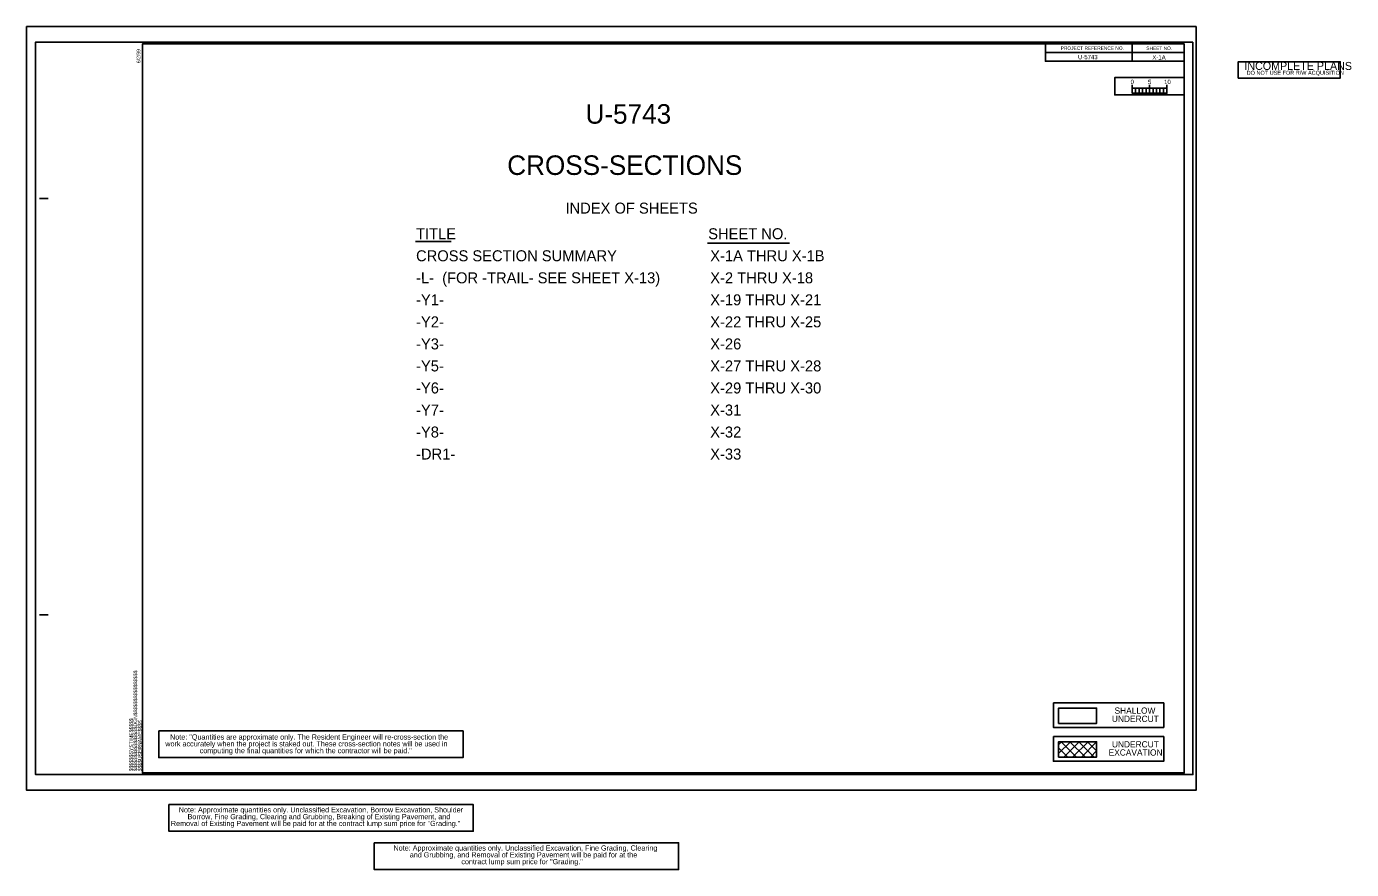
# Model space of a CAD drawing. Extents: x -19 to 363, y -23 to 220.
import ezdxf

# ---------------------------------------------------------------- set-up
doc = ezdxf.new("R2010")
doc.units = 0
for name, color, linetype in [('Old_Level_2', 7, 'Continuous'), ('Old_Level_38', 7, 'Continuous'), ('Old_Level_40', 7, 'Continuous'), ('Old_Level_41', 7, 'Continuous'), ('Prop Grid Mask', 7, 'Continuous'), ('Prop Shade Light', 7, 'Continuous'), ('Prop XS Sheet Number', 7, 'Continuous'), ('Prop XS Undercut Exc Hatch', 7, 'Continuous'), ('Prop XSC Text', 7, 'Continuous'), ('Sheet Cutting Line CELL', 7, 'Continuous'), ('Sheet Plot Border Inside CELL', 7, 'Continuous'), ('Sheet Plot Border Outside CELL', 7, 'Continuous'), ('Sheet Sticker Incomplete CELL', 7, 'Continuous'), ('Sheet Summary Combination CELL', 7, 'Continuous'), ('Sheet Typical CELL', 7, 'Continuous')]:
    doc.layers.add(name, color=color, linetype=linetype)

msp = doc.modelspace()

# ---------------------------------------------------------------- linework, layer by layer
at = {"layer": 'Old_Level_2'}
for points in [[(276.77, 25.16), (308.55, 25.16), (308.55, 18.08), (276.77, 18.08)], [(278.24, 19.25), (289.22, 19.25), (289.22, 23.69), (278.24, 23.69)]]:
    msp.add_lwpolyline(points, close=True, dxfattribs=at)
at = {"layer": 'Old_Level_38'}
for p, q in [((299.45, 200.79), (299.45, 203.2)), ((299.45, 202.2), (299.45, 203.2)), ((304.45, 200.79), (304.45, 203.2)), ((309.45, 200.79), (309.45, 203.2)), ((309.45, 202.2), (309.45, 203.2))]:
    msp.add_line(p, q, dxfattribs=at)
for points in [[(309.45, 202.2), (299.45, 202.2), (299.45, 200.79), (309.45, 200.79)], [(299.45, 202.2), (300.45, 202.2), (300.45, 200.79), (299.45, 200.79)], [(301.45, 202.2), (302.45, 202.2), (302.45, 200.79), (301.45, 200.79)], [(303.45, 202.2), (304.45, 202.2), (304.45, 200.79), (303.45, 200.79)], [(305.45, 202.2), (306.45, 202.2), (306.45, 200.79), (305.45, 200.79)], [(307.45, 202.2), (308.45, 202.2), (308.45, 200.79), (307.45, 200.79)]]:
    msp.add_lwpolyline(points, close=True, dxfattribs=at)
at = {"layer": 'Old_Level_40'}
msp.add_line((314.45, 202.8), (314.45, 200.3), dxfattribs=at)
msp.add_lwpolyline([(314.45, 205.3), (294.45, 205.3), (294.45, 200.3), (314.45, 200.3)], close=True, dxfattribs=at)
at = {"layer": 'Old_Level_41'}
msp.add_line((294.45, 205.3), (294.45, 200.33), dxfattribs=at)
at = {"layer": 'Prop Grid Mask'}
for points in [[(19.11, 17.1), (106.78, 17.1), (106.78, 9.41), (19.11, 9.41)], [(276.77, 15.46), (308.55, 15.46), (308.55, 8.38), (276.77, 8.38)], [(278.24, 9.55), (289.22, 9.55), (289.22, 13.99), (278.24, 13.99)], [(22.04, -4.14), (109.72, -4.14), (109.72, -11.82), (22.04, -11.82)], [(81.17, -15.14), (168.84, -15.14), (168.84, -22.83), (81.17, -22.83)]]:
    msp.add_lwpolyline(points, close=True, dxfattribs=at)
at = {"layer": 'Prop Shade Light'}
for p, q in [((278.24, 19.36), (278.34, 19.25)), ((278.34, 19.25), (289.22, 19.25))]:
    msp.add_line(p, q, dxfattribs=at)
msp.add_lwpolyline([(289.22, 19.25), (289.22, 23.69), (278.24, 23.69), (278.24, 19.36)], dxfattribs=at)
at = {"layer": 'Prop XS Undercut Exc Hatch'}
for p, q in [((278.24, 19.36), (278.34, 19.25)), ((278.24, 13.11), (279.12, 13.99)), ((278.24, 10.56), (281.66, 13.99)), ((278.24, 12.2), (280.89, 9.55)), ((278.99, 13.99), (283.43, 9.55)), ((279.77, 9.55), (284.21, 13.99)), ((281.54, 13.99), (285.98, 9.55)), ((282.31, 9.55), (286.75, 13.99)), ((284.08, 13.99), (288.52, 9.55)), ((284.86, 9.55), (289.22, 13.91)), ((286.63, 13.99), (289.22, 11.4)), ((289.18, 13.99), (289.22, 13.95)), ((278.24, 9.65), (278.34, 9.55)), ((287.4, 9.55), (289.22, 11.36))]:
    msp.add_line(p, q, dxfattribs=at)
at = {"layer": 'Sheet Cutting Line CELL'}
for p, q in [((317.85, 220.01), (-18.95, 220.01)), ((-18.95, 220.01), (-18.95, 0.01)), ((-18.95, 0.01), (317.85, 0.01))]:
    msp.add_line(p, q, dxfattribs=at)
at = {"layer": 'Sheet Plot Border Inside CELL'}
msp.add_lwpolyline([(316.95, 215.52), (-16.35, 215.52), (-16.35, 4.5), (316.95, 4.5)], close=True, dxfattribs=at)
at = {"layer": 'Sheet Plot Border Outside CELL'}
msp.add_lwpolyline([(317.85, 220.01), (-18.95, 220.01), (-18.95, 0.01), (317.85, 0.01)], close=True, dxfattribs=at)
at = {"layer": 'Sheet Sticker Incomplete CELL'}
msp.add_lwpolyline([(329.97, 205.16), (329.97, 209.86), (359.37, 209.86), (359.37, 205.16)], close=True, dxfattribs=at)
at = {"layer": 'Sheet Summary Combination CELL'}
for p, q in [((93.08, 158.09), (103.37, 158.09)), ((177.16, 157.57), (200.73, 157.57))]:
    msp.add_line(p, q, dxfattribs=at)
at = {"layer": 'Sheet Typical CELL'}
for p, q in [((299.45, 215), (299.45, 210)), ((274.44, 212.5), (314.45, 212.5)), ((-15.25, 170.51), (-12.75, 170.51)), ((-15.25, 50.51), (-12.75, 50.51)), ((14.45, 5.01), (14.45, 5.01)), ((14.45, 5.01), (14.45, 5.01)), ((14.45, 5.01), (14.45, 5.01)), ((14.45, 5.01), (14.45, 5.01)), ((14.45, 5.01), (14.45, 5.01)), ((14.45, 5.01), (14.45, 5.01))]:
    msp.add_line(p, q, dxfattribs=at)
for points in [[(314.45, 215.01), (14.45, 215.01), (14.45, 5.01), (314.45, 5.01)], [(274.44, 215.01), (314.45, 215.01), (314.45, 210), (274.44, 210)]]:
    msp.add_lwpolyline(points, close=True, dxfattribs=at)

# ---------------------------------------------------------------- texts
at = {"layer": 'Old_Level_38'}
for s, p in [('0', (298.99, 203.42)), ('5', (304.01, 203.42)), ('10', (308.64, 203.42))]:
    msp.add_text(s, height=1.25, dxfattribs=at).set_placement(p)
at = {"layer": 'Old_Level_40'}
msp.add_text('U-5743', height=1.25, dxfattribs=at).set_placement((283.84, 210.58))
at = {"layer": 'Prop XS Sheet Number'}
msp.add_text('X-1A', height=1.25, dxfattribs=at).set_placement((305.26, 210.5))
at = {"layer": 'Prop XSC Text'}
for s, height, p in [('SHALLOW', 1.8, (294.37, 22.04)), ('UNDERCUT', 1.8, (293.6, 19.68)), ('Note: "Quantities are approximate only. The Resident Engineer will re-cross-section the', 1.5, (22.39, 14.6)), ('work accurately when the project is staked out. These cross-section notes will be used in', 1.5, (21.02, 12.64)), ('computing the final quantities for which the contractor will be paid."', 1.5, (30.93, 10.67)), ('EXCAVATION', 1.8, (292.67, 9.98)), ('UNDERCUT', 1.8, (293.61, 12.34)), ('Note: Approximate quantities only. Unclassified Excavation, Borrow Excavation, Shoulder', 1.5, (24.9, -6.38)), ('Borrow, Fine Grading, Clearing and Grubbing, Breaking of Existing Pavement, and', 1.5, (27.43, -8.34)), ('Removal of Existing Pavement will be paid for at the contract lump sum price for "Grading."', 1.5, (22.63, -10.31)), ('Note: Approximate quantities only. Unclassified Excavation, Fine Grading, Clearing ', 1.5, (86.73, -17.38)), ('and Grubbing, and Removal of Existing Pavement will be paid for at the ', 1.5, (91.41, -19.35)), ('contract lump sum price for "Grading."', 1.5, (106.27, -21.31))]:
    msp.add_text(s, height=height, dxfattribs=at).set_placement(p)
at = {"layer": 'Sheet Sticker Incomplete CELL'}
for s, height, p in [('INCOMPLETE PLANS', 2.304, (331.76, 207.5)), ('DO NOT USE FOR R/W ACQUISITION', 1.152, (332.41, 206.11))]:
    msp.add_text(s, height=height, dxfattribs=at).set_placement(p)
at = {"layer": 'Sheet Summary Combination CELL'}
for s, height, p in [('U-5743', 5.625, (142.02, 192.01)), ('CROSS-SECTIONS', 5.625, (119.48, 177.25)), ('INDEX OF SHEETS', 3.1641, (136.26, 166.11)), ('TITLE', 3.164, (93.23, 158.73)), ('SHEET NO.', 3.164, (177.36, 158.73)), ('CROSS SECTION SUMMARY', 3.1641, (93.23, 152.38)), ('X-1A THRU X-1B', 3.1641, (177.94, 152.38)), ('-L-  (FOR -TRAIL- SEE SHEET X-13)', 3.1641, (93.23, 146.03)), ('X-2 THRU X-18', 3.1641, (177.94, 146.03)), ('-Y1-', 3.164, (93.23, 139.69)), ('X-19 THRU X-21', 3.1641, (177.94, 139.69)), ('-Y2-', 3.164, (93.23, 133.34)), ('X-22 THRU X-25', 3.1641, (177.94, 133.34)), ('-Y3-', 3.164, (93.23, 126.99)), ('X-26 ', 3.164, (177.94, 126.99)), ('-Y5-', 3.164, (93.23, 120.65)), ('X-27 THRU X-28', 3.1641, (177.94, 120.65)), ('-Y6-', 3.164, (93.23, 114.3)), ('X-29 THRU X-30', 3.1641, (177.94, 114.3)), ('-Y7-', 3.164, (93.23, 107.95)), ('X-31', 3.164, (177.94, 107.95)), ('-Y8- ', 3.164, (93.23, 101.61)), ('X-32', 3.164, (177.94, 101.61)), ('-DR1- ', 3.164, (93.23, 95.26)), ('X-33', 3.164, (177.94, 95.26))]:
    msp.add_text(s, height=height, rotation=0.0119, dxfattribs=at).set_placement(p)
at = {"layer": 'Sheet Typical CELL'}
for s, p in [('PROJECT REFERENCE NO.', (278.88, 213.27)), ('SHEET NO.', (303.51, 213.25))]:
    msp.add_text(s, height=1, dxfattribs=at).set_placement(p)
for s, p in [('6/2/99', (13.82, 209.46)), ('$$$$$$$$$$$$$$$$DGN$$$$$$$$$$$$$$$$', (12.92, 5.49)), ('$$$$$$SYSTIME$$$$$', (11.71, 5.49)), ('$$$$USERNAME$$$$', (14.23, 5.49))]:
    msp.add_text(s, height=1.05, rotation=90, dxfattribs=at).set_placement(p)

doc.saveas('drawing.dxf')
